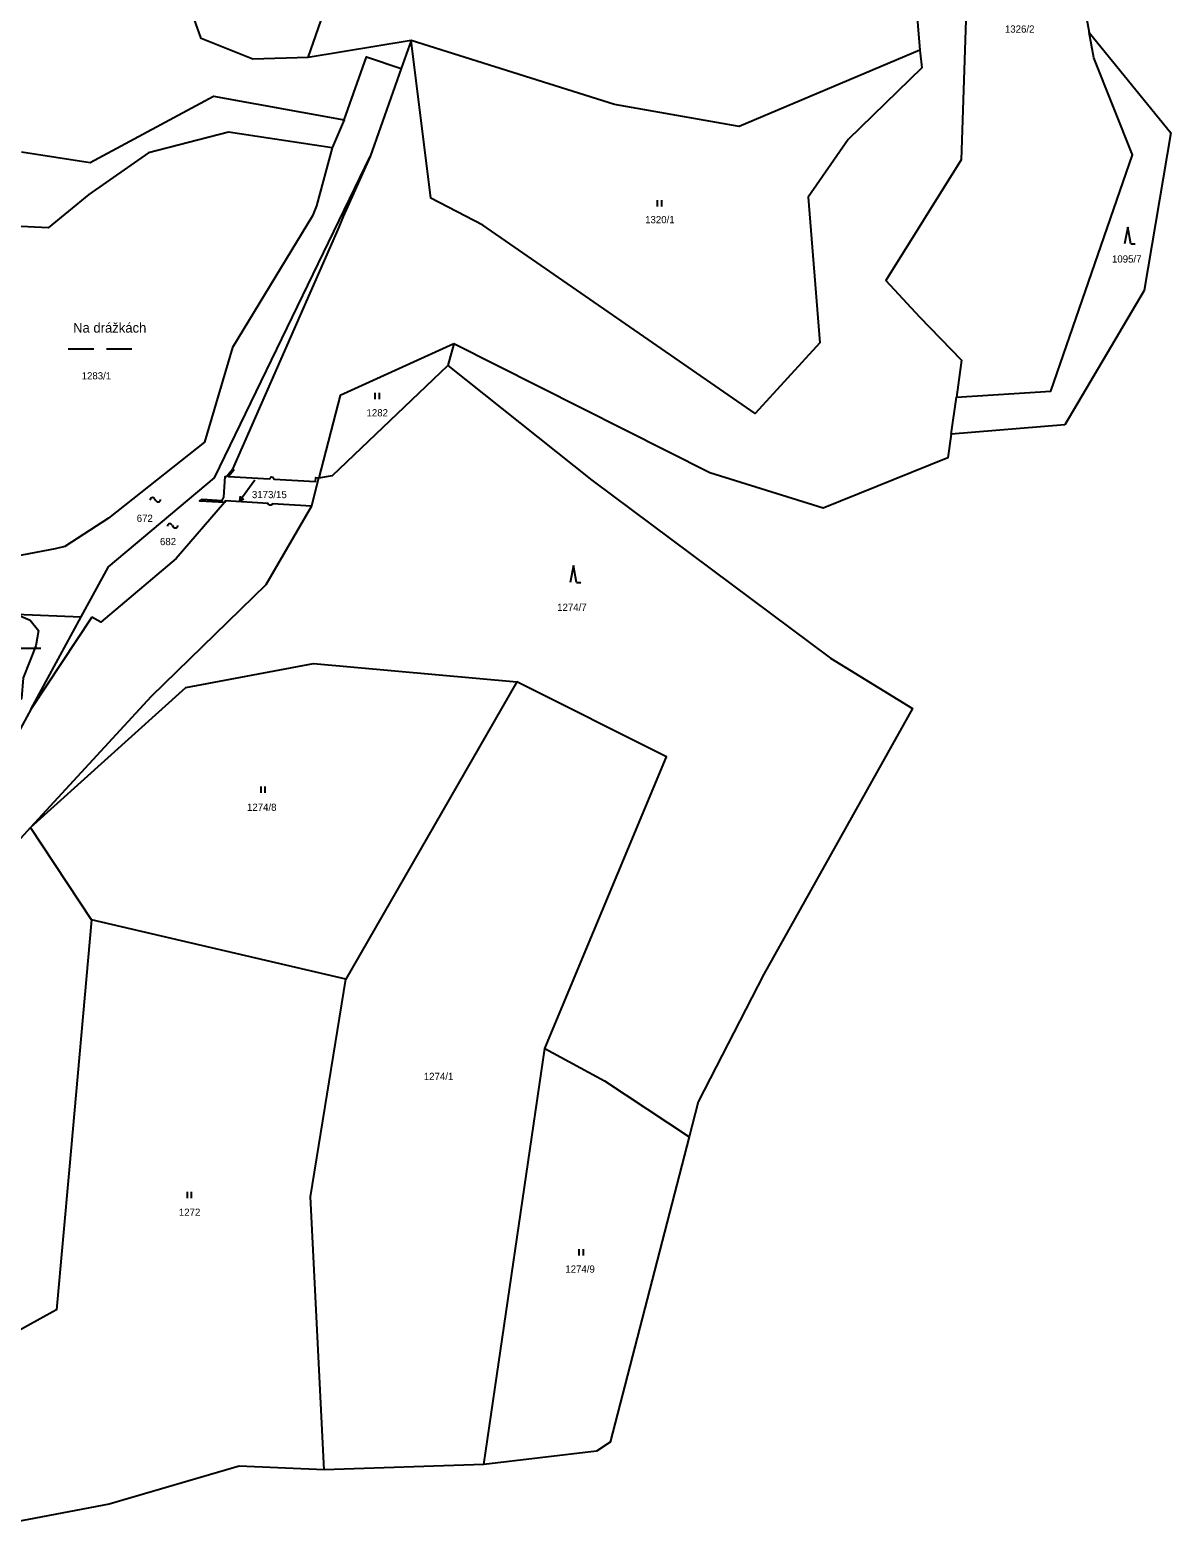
# Model space of a CAD drawing. Extents: x -755528 to -748832, y -1118122 to -1111095.
# Drawn here: x -751731.8 to -751463, y -1116580.8 to -1116225.3 of the extents above; entities that cross this region are included whole.
import ezdxf

# ---------------------------------------------------------------- set-up
doc = ezdxf.new("R2010")
doc.units = 0
for name, color, linetype in [('DZ_DO_PUPFL', 7, 'Continuous'), ('DZ_NAD_ZPF', 7, 'Continuous'), ('legenda barvy', 7, 'Continuous'), ('legenda_text', 7, 'Continuous'), ('TZ_UMVŽST', 7, 'Continuous')]:
    doc.layers.add(name, color=color, linetype=linetype)

msp = doc.modelspace()

# ---------------------------------------------------------------- linework, layer by layer
at = {"layer": 'DZ_NAD_ZPF'}
for p, q in [((-751482.25, -1116225.86), (-751463, -1116249.54)), ((-751642.06, -1116227.76), (-751666.32, -1116231.78)), ((-751642.06, -1116227.76), (-751644.38, -1116234.35)), ((-751666.32, -1116231.78), (-751679.35, -1116232.12)), ((-751644.38, -1116234.35), (-751651.68, -1116255.07)), ((-751657.85, -1116246.46), (-751660.66, -1116253.07)), ((-751733.92, -1116254.03), (-751717.72, -1116256.52)), ((-751660.66, -1116253.07), (-751664.33, -1116266.75)), ((-751632, -1116299.26), (-751633.4, -1116304.36)), ((-751633.4, -1116304.36), (-751599.43, -1116331.41)), ((-751514.75, -1116320.57), (-751513.52, -1116311.81)), ((-751487.97, -1116318.4), (-751514.75, -1116320.57)), ((-751735.12, -1116362.98), (-751719.79, -1116363.61)), ((-751731.6, -1116385.33), (-751719.79, -1116363.61)), ((-751717.34, -1116363.71), (-751731.6, -1116385.33)), ((-751617.15, -1116378.93), (-751657.47, -1116449.09)), ((-751717.41, -1116435.06), (-751731.75, -1116413.32)), ((-751657.47, -1116449.09), (-751717.41, -1116435.06)), ((-751624.89, -1116563.49), (-751610.57, -1116465.43)), ((-751624.89, -1116563.49), (-751662.56, -1116564.75)), ((-751598.33, -1116560.33), (-751624.89, -1116563.49)), ((-751662.56, -1116564.75), (-751682.59, -1116563.89))]:
    msp.add_line(p, q, dxfattribs=at)
for points in [[(-751555.51, -1116101.51), (-751554.01, -1116146.42), (-751551.56, -1116158.03), (-751525.13, -1116193.62), (-751522.15, -1116230.05)], [(-751666.32, -1116231.78), (-751649.98, -1116184.8), (-751637.94, -1116141.45), (-751632.74, -1116114.72)], [(-751528.9, -1116150), (-751520.21, -1116168.79), (-751510.98, -1116213.41), (-751512.44, -1116255.89), (-751530.14, -1116284.35), (-751522.23, -1116292.88), (-751512.36, -1116303.14), (-751513.52, -1116311.81)], [(-751476.66, -1116153.91), (-751488.47, -1116192.53), (-751482.25, -1116225.86)], [(-751679.35, -1116232.12), (-751691.52, -1116227.27), (-751696.53, -1116213.04), (-751698.25, -1116208.08)], [(-751513.52, -1116311.81), (-751491.28, -1116310.41), (-751472.04, -1116254.72), (-751481.13, -1116231.86), (-751482.25, -1116225.86)], [(-751522.15, -1116230.05), (-751564.72, -1116248), (-751594.11, -1116242.86), (-751642.06, -1116227.76)], [(-751522.15, -1116230.05), (-751521.67, -1116234.16), (-751539.04, -1116251.11), (-751548.5, -1116264.72), (-751545.7, -1116299.04), (-751560.95, -1116315.67), (-751625.15, -1116271.3), (-751637.42, -1116264.92), (-751642.06, -1116227.76)], [(-751657.85, -1116246.46), (-751652.54, -1116231.62), (-751644.38, -1116234.35)], [(-751717.72, -1116256.52), (-751688.61, -1116240.85), (-751657.85, -1116246.46)], [(-751660.66, -1116253.07), (-751685.1, -1116249.35), (-751703.96, -1116254.26), (-751717.98, -1116264.08), (-751727.6, -1116271.88), (-751750.07, -1116270.78), (-751754.08, -1116285.35)], [(-751463, -1116249.54), (-751469.3, -1116286.7), (-751487.97, -1116318.4)], [(-751719.79, -1116363.61), (-751713.39, -1116351.84), (-751688.36, -1116330.88), (-751651.68, -1116255.07)], [(-751651.68, -1116255.07), (-751658.05, -1116269.26), (-751659.07, -1116271.73), (-751684.14, -1116328.8)], [(-751664.33, -1116266.75), (-751665.3, -1116269.06), (-751684.14, -1116300.15), (-751690.78, -1116322.45), (-751713.36, -1116340.4), (-751723.69, -1116347.04), (-751725.91, -1116347.59), (-751735.43, -1116349.43), (-751736.04, -1116349.4), (-751754.21, -1116354.2), (-751760.4, -1116356.64), (-751763.1, -1116356.78)], [(-751632, -1116299.26), (-751658.79, -1116311.42), (-751663.78, -1116330.84)], [(-751514.75, -1116320.57), (-751515.53, -1116326.12), (-751544.91, -1116338.02), (-751571.64, -1116329.66), (-751632, -1116299.26)], [(-751663.78, -1116330.84), (-751660.62, -1116330.32), (-751633.4, -1116304.36)], [(-751686, -1116336.68), (-751691.83, -1116336.37), (-751691.84, -1116336.24), (-751691.29, -1116335.92), (-751686.56, -1116336.17), (-751686.2, -1116335.4), (-751685.9, -1116330.53), (-751685.59, -1116330.51), (-751684.14, -1116328.8)], [(-751684.14, -1116328.8), (-751683.85, -1116329.04), (-751685.11, -1116330.54), (-751675.44, -1116331.09), (-751675.02, -1116330.66), (-751674.64, -1116330.69), (-751674.31, -1116331.15), (-751664.57, -1116331.7), (-751664.51, -1116330.8), (-751663.78, -1116330.84)], [(-751665.55, -1116337.52), (-751665.45, -1116337.35), (-751663.78, -1116330.84)], [(-751599.43, -1116331.41), (-751543.19, -1116373.34), (-751523.86, -1116385.21), (-751558.95, -1116447.88), (-751574.4, -1116477.97), (-751576.54, -1116486.23)], [(-751665.55, -1116337.52), (-751674.71, -1116336.97), (-751674.72, -1116337.08), (-751675.13, -1116337.31), (-751675.37, -1116337.28), (-751675.79, -1116337.02), (-751675.78, -1116336.91), (-751685.84, -1116336.3), (-751686, -1116336.68)], [(-751665.55, -1116337.52), (-751676.27, -1116356.1), (-751703.31, -1116382.39), (-751731.75, -1116413.32)], [(-751686, -1116336.68), (-751697.4, -1116349.87), (-751715.19, -1116364.85), (-751717.34, -1116363.71)], [(-751735.12, -1116362.98), (-751731.81, -1116364.39), (-751729.88, -1116366.83), (-751730.48, -1116370.48), (-751733.45, -1116377.98), (-751733.85, -1116382.89), (-751735.22, -1116383.82), (-751742.46, -1116387.5), (-751743.85, -1116386.88), (-751745.52, -1116383.84), (-751745.28, -1116380.99), (-751743.69, -1116377.99), (-751743.05, -1116368.19), (-751742.78, -1116366.04), (-751741.43, -1116363.78), (-751737.8, -1116362.88)], [(-751731.75, -1116413.32), (-751695.12, -1116380.27), (-751665.05, -1116374.6), (-751617.15, -1116378.93)], [(-751610.57, -1116465.43), (-751581.9, -1116396.66), (-751617.15, -1116378.93)], [(-751731.6, -1116385.33), (-751743.92, -1116407.99), (-751798.53, -1116466.86)], [(-751731.75, -1116413.32), (-751739.72, -1116421.97), (-751755.56, -1116439.14)], [(-751717.41, -1116435.06), (-751722.66, -1116494.03), (-751725.6, -1116526.99), (-751726.51, -1116527.49), (-751753.44, -1116542.31), (-751765.29, -1116548.83), (-751759.54, -1116580.77)], [(-751662.56, -1116564.75), (-751665.76, -1116500.39), (-751657.47, -1116449.09)], [(-751610.57, -1116465.43), (-751596.5, -1116473), (-751576.54, -1116486.23)], [(-751576.54, -1116486.23), (-751595.11, -1116558.21), (-751598.33, -1116560.33)], [(-751682.59, -1116563.89), (-751713.25, -1116572.84), (-751741.82, -1116578.24)]]:
    msp.add_lwpolyline(points, dxfattribs=at)
at = {"layer": 'legenda_text'}
for p, q in [((-751702.51, -1116335.83), (-751702.21, -1116336.23)), ((-751698.4, -1116341.98), (-751698.1, -1116342.38))]:
    msp.add_line(p, q, dxfattribs=at)
for centre, start, end in [((-751703.0225, -1116336.1173), 29.291361, 181.218875), ((-751701.6975, -1116335.9423), 209.291358, 1.218872), ((-751698.9125, -1116342.2673), 29.291361, 181.218875), ((-751697.5875, -1116342.0923), 209.291358, 1.218872)]:
    msp.add_arc(centre, 0.5876, start, end, dxfattribs=at)
at = {"layer": 'TZ_UMVŽST'}
for p, q in [((-751584.001, -1116266.88), (-751584.001, -1116265.38)), ((-751583, -1116266.88), (-751583, -1116265.38)), ((-751473.15, -1116271.72), (-751473.9, -1116275.72)), ((-751472.4, -1116275.72), (-751473.15, -1116271.72)), ((-751472.4, -1116275.72), (-751471.404, -1116275.72)), ((-751722.859, -1116300.42), (-751716.859, -1116300.42)), ((-751713.859, -1116300.42), (-751707.859, -1116300.42)), ((-751650.521, -1116312.3), (-751650.521, -1116310.8)), ((-751649.52, -1116312.3), (-751649.52, -1116310.8)), ((-751678.904, -1116331.422), (-751682.43, -1116336.276)), ((-751682.43, -1116336.276), (-751682.262, -1116335.191)), ((-751682.43, -1116336.276), (-751681.45, -1116335.78)), ((-751603.81, -1116351.56), (-751604.56, -1116355.56)), ((-751603.06, -1116355.56), (-751603.81, -1116351.56)), ((-751603.06, -1116355.56), (-751602.064, -1116355.56)), ((-751735.309, -1116371.05), (-751729.309, -1116371.05)), ((-751677.431, -1116405.16), (-751677.431, -1116403.66)), ((-751676.43, -1116405.16), (-751676.43, -1116403.66)), ((-751694.781, -1116500.71), (-751694.781, -1116499.21)), ((-751693.78, -1116500.71), (-751693.78, -1116499.21)), ((-751602.441, -1116514.18), (-751602.441, -1116512.68)), ((-751601.44, -1116514.18), (-751601.44, -1116512.68))]:
    msp.add_line(p, q, dxfattribs=at)

# ---------------------------------------------------------------- texts
at = {"layer": 'DZ_DO_PUPFL'}
for s, p in [('1326/2', (-751502.1, -1116225.9)), ('1320/1', (-751586.9, -1116270.83)), ('1095/7', (-751476.87, -1116280.11)), ('1283/1', (-751719.697, -1116307.65)), ('1282', (-751652.57, -1116316.37)), ('3173/15', (-751679.576, -1116335.65)), ('672', (-751706.725, -1116341.25)), ('682', (-751701.245, -1116346.73)), ('1274/7', (-751607.63, -1116362.23)), ('1274/8', (-751680.74, -1116409.37)), ('1274/1', (-751639.06, -1116472.83)), ('1272', (-751696.79, -1116504.85)), ('1274/9', (-751605.71, -1116518.25))]:
    msp.add_text(s, height=1.7, dxfattribs=at).set_placement(p)
at = {"layer": 'legenda barvy'}
msp.add_text('Na drážkách', height=2.299998, dxfattribs=at).set_placement((-751721.72, -1116296.62))

doc.saveas('drawing.dxf')
